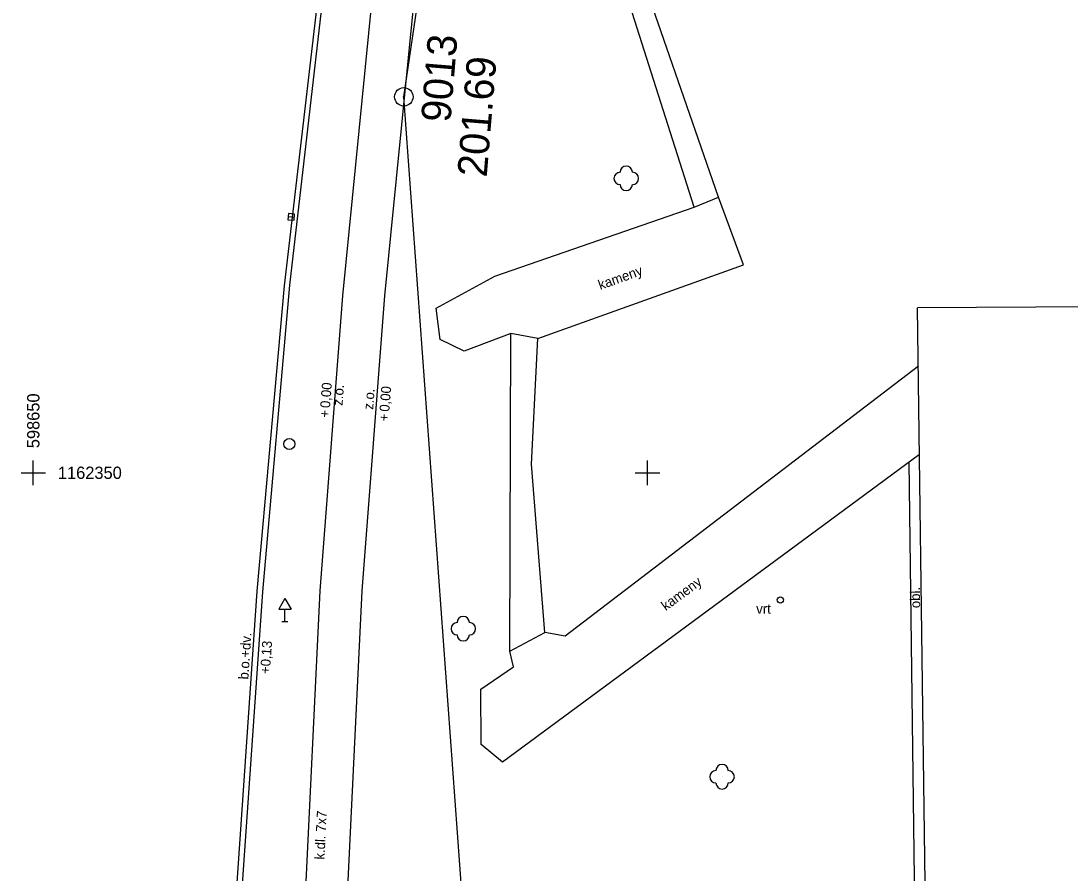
# Model space of a CAD drawing. Extents: x -598693 to -598240, y -1162454 to -1160800.
# Drawn here: x -598650.5 to -598607.77, y -1162366.3 to -1162331.6 of the extents above; entities that cross this region are included whole.
import ezdxf

# ---------------------------------------------------------------- set-up
doc = ezdxf.new("R2010")
doc.units = 0
for name, color, linetype in [('Vrstva 14', 7, 'Continuous'), ('Vrstva 15', 7, 'Continuous'), ('Vrstva 19', 7, 'Continuous'), ('Vrstva 2', 7, 'Continuous'), ('Vrstva 25', 7, 'Continuous'), ('Vrstva 4', 7, 'Continuous'), ('Vrstva 40', 7, 'Continuous'), ('Vrstva 44', 7, 'Continuous'), ('Vrstva 49', 7, 'Continuous'), ('Vrstva 50', 7, 'Continuous'), ('Vrstva 61', 7, 'Continuous'), ('Vrstva 62', 7, 'Continuous'), ('Vrstva 7', 7, 'Continuous')]:
    doc.layers.add(name, color=color, linetype=linetype)

msp = doc.modelspace()

# ---------------------------------------------------------------- linework, layer by layer
at = {"layer": 'Vrstva 14'}
for centre in [(-598625.87, -1162338.01), (-598632.5, -1162356.35), (-598621.97, -1162362.38)]:
    msp.add_circle(centre, 0.00025, dxfattribs=at)
for centre, start, end in [((-598625.87, -1162337.76), 0, 180), ((-598626.12, -1162338.01), 90, 270), ((-598625.62, -1162338.01), 270, 90), ((-598625.87, -1162338.26), 180, 360), ((-598632.5, -1162356.1), 0, 180), ((-598632.75, -1162356.35), 90, 270), ((-598632.25, -1162356.35), 270, 90), ((-598632.5, -1162356.6), 180, 360), ((-598621.97, -1162362.13), 0, 180), ((-598622.22, -1162362.38), 90, 270), ((-598621.72, -1162362.38), 270, 90), ((-598621.97, -1162362.63), 180, 360)]:
    msp.add_arc(centre, 0.25, start, end, dxfattribs=at)
at = {"layer": 'Vrstva 15'}
for radius in [0.125, 0.125, 0.00025, 0.00025]:
    msp.add_circle((-598619.6, -1162355.18), radius, dxfattribs=at)
at = {"layer": 'Vrstva 19'}
for p, q in [((-598639.76, -1162355.127), (-598640.01, -1162355.56)), ((-598639.76, -1162355.127), (-598639.51, -1162355.56)), ((-598640.01, -1162355.56), (-598639.51, -1162355.56)), ((-598639.76, -1162356.06), (-598639.76, -1162355.56)), ((-598639.885, -1162356.06), (-598639.635, -1162356.06))]:
    msp.add_line(p, q, dxfattribs=at)
at = {"layer": 'Vrstva 2'}
for radius in [0.375, 0.375, 0.0179, 0.0179]:
    msp.add_circle((-598634.92, -1162334.69), radius, dxfattribs=at)
at = {"layer": 'Vrstva 25'}
msp.add_line((-598639.625, -1162339.569), (-598639.375, -1162339.591), dxfattribs=at)
msp.add_lwpolyline([(-598639.636, -1162339.693), (-598639.387, -1162339.716), (-598639.364, -1162339.467), (-598639.613, -1162339.444)], close=True, dxfattribs=at)
at = {"layer": 'Vrstva 4'}
msp.add_line((-598585.94, -1162343.12), (-598614.01, -1162343.28), dxfattribs=at)
msp.add_lwpolyline([(-598585.36, -1162381.62), (-598613.5, -1162382), (-598614.01, -1162343.28)], dxfattribs=at)
at = {"layer": 'Vrstva 40'}
msp.add_lwpolyline([(-598613.979, -1162345.662), (-598628.36, -1162356.65), (-598629.18, -1162356.5), (-598629.72, -1162349.65), (-598629.47, -1162344.53), (-598621.1, -1162341.53), (-598622.11, -1162338.77), (-598625.74, -1162328.31), (-598625.9, -1162326.25), (-598625.32, -1162325.88), (-598604.36, -1162323.38), (-598591.96, -1162321.1), (-598574.34, -1162317.76), (-598571.64, -1162319.3)], dxfattribs=at)
at = {"layer": 'Vrstva 44'}
msp.add_circle((-598639.58, -1162348.83), 0.225, dxfattribs=at)
at = {"layer": 'Vrstva 61'}
for p, q in [((-598634.92, -1162334.69), (-598624.77, -1162266.32)), ((-598630.05, -1162401.44), (-598634.92, -1162334.69))]:
    msp.add_line(p, q, dxfattribs=at)
at = {"layer": 'Vrstva 62'}
for p, q in [((-598650, -1162350.5), (-598650, -1162349.5)), ((-598625, -1162350.5), (-598625, -1162349.5)), ((-598650.5, -1162350), (-598649.5, -1162350)), ((-598625.5, -1162350), (-598624.5, -1162350))]:
    msp.add_line(p, q, dxfattribs=at)
at = {"layer": 'Vrstva 7'}
for points in [[(-598641.85, -1162368.87), (-598640.89, -1162354.82), (-598639.77, -1162342.39), (-598638.09, -1162327.94), (-598636.27, -1162314.81), (-598633.66, -1162298.25), (-598631.01, -1162281.94), (-598629.73, -1162274.35), (-598627.69, -1162262.68), (-598625.61, -1162252.57), (-598622.66, -1162240.21), (-598619.84, -1162229.62), (-598617.59, -1162221.85), (-598616.2, -1162218.11), (-598614.88, -1162215.94), (-598613.48, -1162214.36), (-598611.94, -1162212.96), (-598610.28, -1162211.84)], [(-598641.63, -1162368.9), (-598640.66, -1162354.85), (-598639.56, -1162342.36), (-598637.91, -1162327.99), (-598636.01, -1162314.87), (-598633.44, -1162298.3), (-598630.79, -1162281.96), (-598629.53, -1162274.37), (-598627.49, -1162262.66), (-598625.39, -1162252.64), (-598622.47, -1162240.28), (-598619.61, -1162229.68), (-598617.41, -1162221.98), (-598616.01, -1162218.23), (-598614.7, -1162216.05), (-598613.35, -1162214.55), (-598611.83, -1162213.18), (-598609.99, -1162211.92)], [(-598638.96, -1162368.06), (-598638.32, -1162354.81), (-598637.4, -1162342.79), (-598635.95, -1162328.11), (-598634.31, -1162315.18), (-598631.8, -1162298.34), (-598629.17, -1162281.88), (-598627.94, -1162274.63), (-598625.78, -1162263.11), (-598623.41, -1162253.07), (-598620.13, -1162241.17), (-598617.07, -1162230.77), (-598615.47, -1162225.15), (-598613.93, -1162220.4), (-598612.82, -1162217.61), (-598611.07, -1162214), (-598609.99, -1162211.92)], [(-598637.26, -1162368.02), (-598636.62, -1162354.81), (-598635.7, -1162342.8), (-598634.26, -1162328.31), (-598632.55, -1162314.89), (-598630.15, -1162298.57), (-598627.52, -1162282.43), (-598626.26, -1162274.97), (-598624.14, -1162263.43), (-598621.73, -1162253.34), (-598618.54, -1162241.79), (-598615.46, -1162231.17), (-598613.83, -1162225.64), (-598612.21, -1162220.66), (-598611.27, -1162218.28), (-598609.98, -1162215.62), (-598609.03, -1162214.43), (-598607.87, -1162213.42)], [(-598613.931, -1162349.251), (-598630.91, -1162361.79), (-598631.77, -1162361.06), (-598631.78, -1162358.82), (-598630.46, -1162357.9), (-598630.61, -1162357.26), (-598630.56, -1162344.33), (-598632.47, -1162345.05), (-598633.44, -1162344.57), (-598633.61, -1162343.3), (-598631.22, -1162342), (-598623.11, -1162339.18), (-598627.56, -1162325.19)], [(-598623.11, -1162339.18), (-598622.11, -1162338.77)], [(-598629.47, -1162344.53), (-598630.56, -1162344.33)], [(-598613.94, -1162382.42), (-598614.35, -1162349.56)], [(-598630.61, -1162357.26), (-598629.18, -1162356.5)]]:
    msp.add_lwpolyline(points, dxfattribs=at)

# ---------------------------------------------------------------- texts
at = {"layer": 'Vrstva 2'}
for s, p in [(' 9013', (-598633.064, -1162336.199)), ('201.69 ', (-598631.549, -1162337.986))]:
    msp.add_text(s, height=1.2, rotation=85.2787, dxfattribs=at).set_placement(p)
at = {"layer": 'Vrstva 49'}
for s, rotation, p in [('kameny', 19.7188, (-598626.926, -1162342.556)), ('z.o.', 85.6232, (-598637.419, -1162347.278)), ('z.o.', 85.6195, (-598636.171, -1162347.443)), ('kameny', 36.4469, (-598624.26, -1162355.636)), ('obl.', 90.7546, (-598613.908, -1162355.511)), ('b.o.+dv.', 86.0506, (-598641.249, -1162358.43)), ('k.dl. 7x7', 87.2263, (-598638.152, -1162365.761))]:
    msp.add_text(s, height=0.4, rotation=rotation, dxfattribs=at).set_placement(p)
msp.add_text('vrt', height=0.4, dxfattribs=at).set_placement((-598620.58, -1162355.74))
at = {"layer": 'Vrstva 50'}
for s, rotation, p in [('0,00', 85.6232, (-598637.927, -1162347.376)), ('0,00', 85.6195, (-598635.513, -1162347.526)), ('+', 85.6232, (-598637.957, -1162347.768)), ('+', 85.6195, (-598635.543, -1162347.918)), ('+0,13', 86.0506, (-598640.374, -1162358.206))]:
    msp.add_text(s, height=0.4, rotation=rotation, dxfattribs=at).set_placement(p)
at = {"layer": 'Vrstva 62'}
msp.add_text('598650', height=0.5, rotation=90, dxfattribs=at).set_placement((-598649.75, -1162349))
msp.add_text('1162350', height=0.5, dxfattribs=at).set_placement((-598649, -1162350.25))

doc.saveas('drawing.dxf')
